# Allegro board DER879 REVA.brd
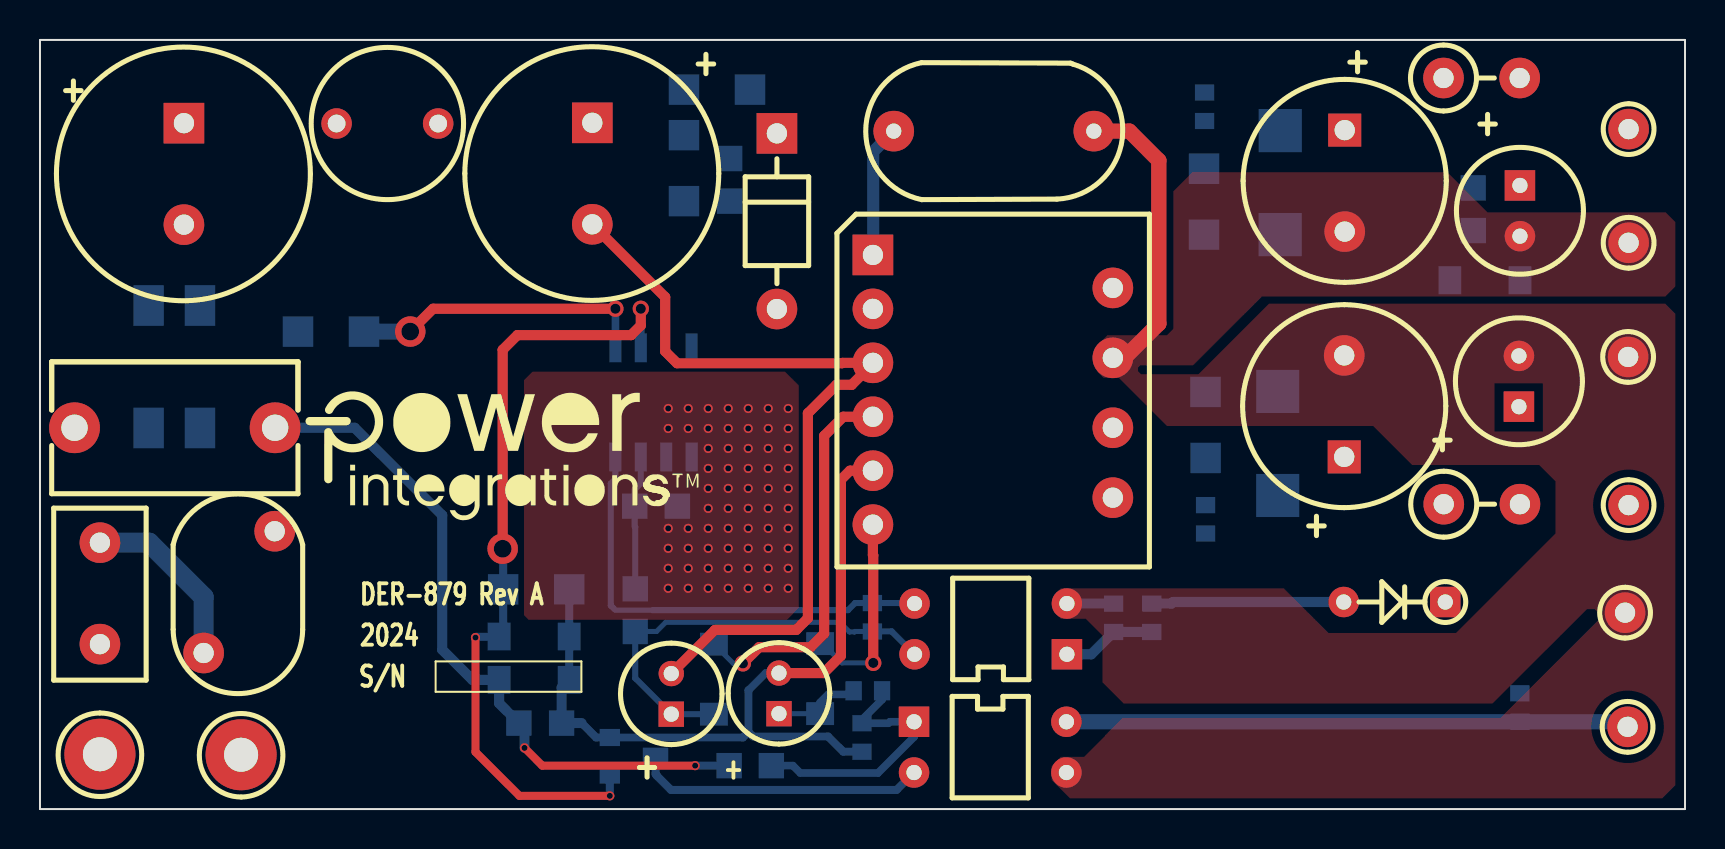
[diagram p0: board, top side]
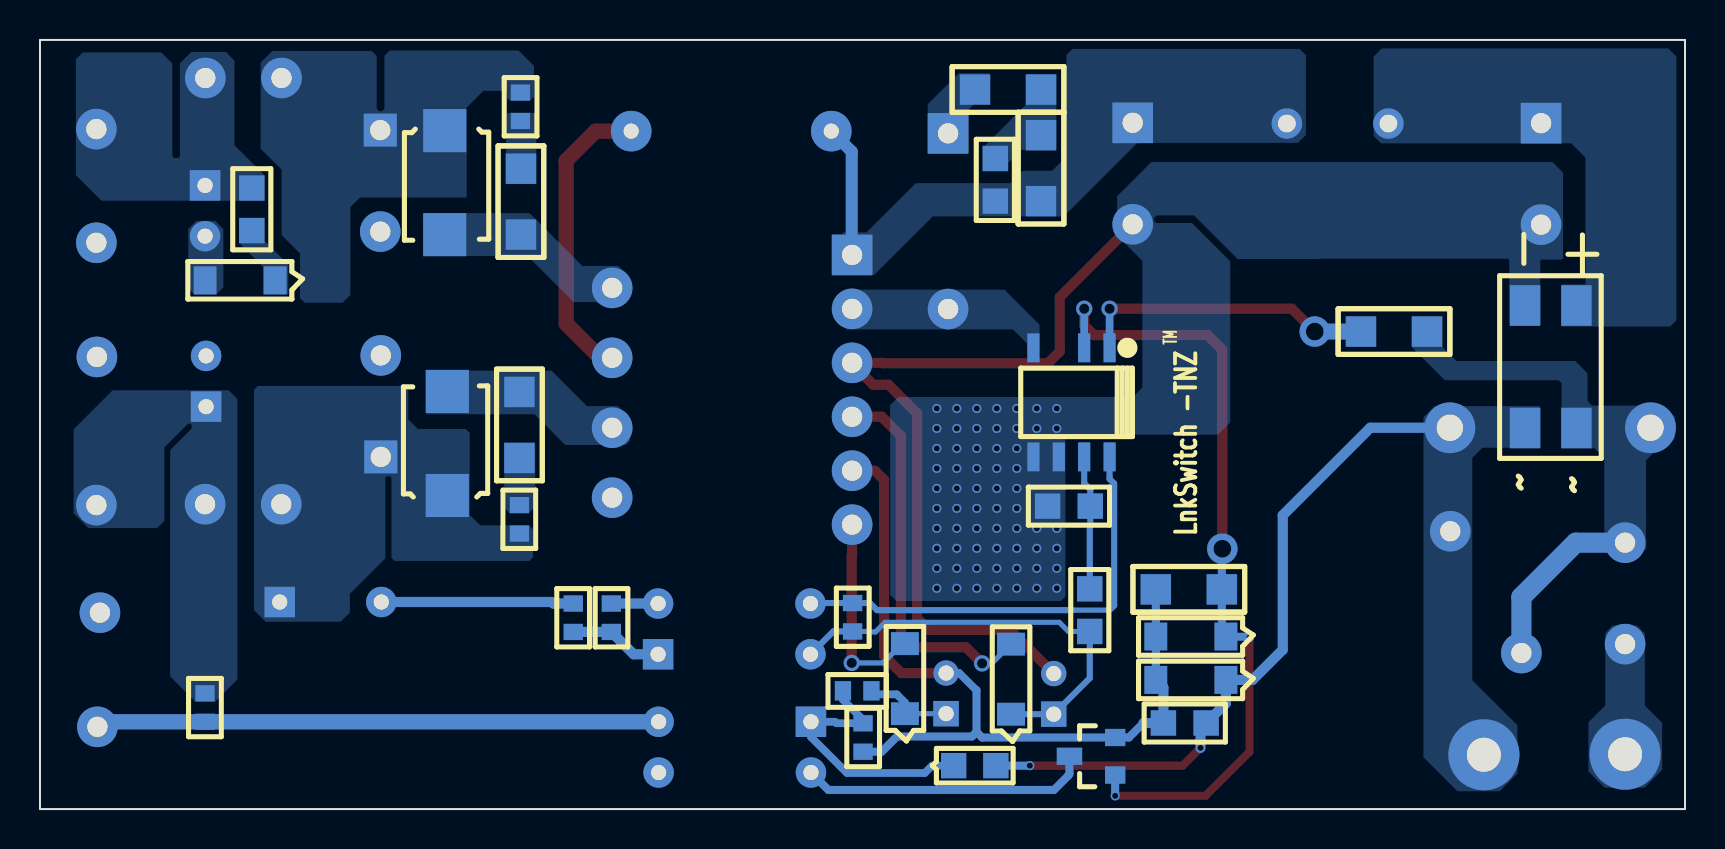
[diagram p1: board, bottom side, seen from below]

Outline 82.27 x 38.5 mm; copper layers: TOP, BOTTOM. Coordinates in mm from the lower left corner of the outline.
Outline path: 0,38.5 0,0 82.27,0 82.27,38.5 0,38.5

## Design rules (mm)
constraint set DEFAULT: min track width 0.508

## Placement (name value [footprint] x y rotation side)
BR1  B10S-G  [PISMSOIC4]  8 19.08 180 bottom
C1  10 uF  [PIPOLCAPCLYD500LS200040]  7.2 34.33 270 top
C2  10 uF  [PIPOLCAPCLYD500LS200040]  27.62 34.35 270 top
C3  2.2 nF  [PISMC0805]  34.49 30.43 90 bottom
C4  1000 pF  [PISMC0603]  58.29 15.21 270 bottom
C5  680 uF  [PIPOLCAPCYLD400LS200040]  65.23 17.63 90 top
C6  120 uF  [PIPOLCAPCYLD250LS100030]  73.96 20.14 90 top
C7  10 uF  [PIPOLCAPCLYD200LS80030]  31.57 4.75 90 top
C8  1 uF  [PISMC0805]  29.74 15.16 0 bottom
C9  1 nF  [PISMC0603]  41.63 8.89 90 bottom
C10  10 uF  [PIPOLCAPCLYD200LS80030]  36.96 4.78 90 top
C11  330 pF  [PINPCAPRAD394X275394030]  42.7 33.93 0 top
C12  680 uF  [PIPOLCAPCYLD400LS200040]  65.25 33.99 270 top
C13  1000 pF  [PISMC0603]  58.24 34.44 90 bottom
C14  120 uF  [PIPOLCAPCYLD250LS100030]  74.02 31.22 270 top
C15  100 nF  [PINPXCAPRAD475X255395040]  1.73 19.09 0 top
C16  100 nF  [PISMC0603]  41.11 2.87 90 bottom
D1  B280-13-F  [PISMSMB]  61.9 15.7 90 bottom
D2  1N4007GP  [PIDV200X110X040DO41]  36.86 34.82 270 top
D3  1N4148W RHG  [PI_SM_SOD-123_12]  33.71 4.75 90 bottom
D4  1N4148W RHG  [PI_SM_SOD-123_12]  39.01 4.78 90 bottom
D5  SS2H10-E3/52T  [PISMSMB]  62.03 33.96 270 bottom
D6  1N4148WS  [PISMDSOD323]  36.58 2.17 180 bottom
F1  1 A  [PI_RST_MICROFUSE]  3 8.26 90 top
L  BLK  [PITPKEYSTONE125X125]  3 2.74 0 top
L1  1 mH  [PICHOKE030DIALS200035]  14.83 34.32 0 top
L2  Ferrite Bead  [PI12WRESD180LS675D040]  70.21 15.26 0 top
L3  Ferrite Bead  [PI12WRESD180LS675D040]  70.19 36.59 0 top
N  WHT  [PITPKEYSTONE125X125]  10.06 2.72 0 top
NOREF  -  []  -228.6 -144.78 0 top
NOREF#2  -  []  -150.78 54.23 0 top
NOREF#3  -  []  82.27 0 90 top
NOREF#4  -  []  13.28 20.88 0 top
NOREF#5  -  []  0 38.5 0 top
Q1  2N7002  [PISMSOT23123_1]  28.5 3.58 90 bottom
R2  51  [PISMR1206]  32.21 36.02 0 bottom
R3  51 k  [PISMR1206]  32.21 30.43 90 bottom
R4  100  [PISMR1206]  58.29 17.58 90 bottom
R5  332  [PISMR0603]  55.6 10.29 270 bottom
R6  1 k  [PISMR0603]  53.7 8.86 90 bottom
R7  51 k  [PISMR0805]  29.77 11.02 270 bottom
R8  510 k  [PISMR1206]  12.9 23.9 0 bottom
R9  240 k  [PISMR1206]  26.47 11 180 bottom
R11  51 k  [PISMR0603]  74.02 5.79 270 bottom
R12  100  [PISMR1206]  58.22 32.05 270 bottom
R13  100  [PISMR0805]  71.68 31.09 270 bottom
R17  510 k  [PISMR0805]  23.95 4.31 0 bottom
R18  1 k  [PISMR0603]  42.11 5.92 180 bottom
RTN_ZCD  BLK  [PITPKEYSTONE100X100]  79.27 9.83 0 top
RV1  300 Vac  [PIDISC350X225LS240X140040]  8.18 7.81 90 top
T1  EE19  [PI_BOBBIN_EE19_10P]  41.66 27.74 0 top
U1  LNK3307  [PISMSO8_NOP3]  28.78 23.09 0 bottom
U2  PS2501-1-H-A  [PI_DIP4]  51.36 7.75 90 top
U3  LTV817D  [PI_DIP4]  43.71 4.37 270 top
UNK5V_RTN  BLK  [PITPKEYSTONE100X100]  79.43 22.63 0 top
UNK12V_RTN  BLK  [PITPKEYSTONE100X100]  79.45 28.35 0 top
UNK+5V  RED  [PITPKEYSTONE100X100]  79.45 15.21 0 top
UNK+12V  RED  [PITPKEYSTONE100X100]  79.45 34.04 0 top
VR2  BZX79-B4V3  [PIDV200X080X030DO35]  70.28 10.36 180 top
VR3  MMSZ4693T1G  [PI_SM_SOD-123_12]  22.96 8.64 0 bottom
VR4  MMSZ5245B-7-F  [PI_SM_SOD-123_12]  70.51 26.47 0 bottom
VR5  MMSZ4693T1G  [PI_SM_SOD-123_12]  22.96 6.46 0 bottom
ZCD  BLUE  [PITPKEYSTONE100X100]  79.4 4.11 0 top

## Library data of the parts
BR1 = DIODE BRIDGE_~~+-: alternate symbols: (pi_sm_soic4_slot)
C1 C2 = CAP POL: alternate symbols: (pipolcapclyd500ls200040800lh)
C3 C4 C8 C9 C11 C13 C16 = CAP NP
C5 C12 = CAP POL: alternate symbols: (pipolcapclyd395x630ls200030h)
C6 C14 = CAP POL: alternate symbols: (pipolcapcyld250ls100030h)
C7 C10 = CAP POL: alternate symbols: (pipolcapclyd200ls80030h)
C15 = CAP NP: alternate symbols: (pinpxcaprad475x255395040_h)
D1 D5 = DIODE SCHOTTKY
D2 = DIODE: alternate symbols: (pidax475x125040do41,pidv200x110x040do41wbead,pidax390x125040do41)
D3 D4 = DIODE: alternate symbols: (pi_sm_sod-123_12_1)
D6 = DIODE
F1 = FUSE: alternate symbols: (pirstmicrofusehoz)
L N RTN_ZCD UNK5V_RTN UNK12V_RTN UNK+5V UNK+12V ZCD = TESTPOINT
L1 = INDUCTOR
L2 L3 = INDUCTOR: alternate symbols: (pi12wvresd180ls150d040,pi12wvresd180ls200d040,pi12wvresd180ls250d040)
Q1 = FET_N_GSD
R2-R9 R11-R13 R17 R18 = R
RV1 = VARISTOR
T1 = BEE19_10P/TF1939
U1 = LNK-TNZ
U2 U3 = OPTO_A_B
VR2 = DIODE_ZENER: alternate symbols: (pidax375x070030do35)
VR3-VR5 = DIODE_ZENER

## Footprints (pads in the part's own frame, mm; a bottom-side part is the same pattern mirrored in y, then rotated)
PI12WRESD180LS675D040
  round 2.032 hole 1.016: 1(0,0) 2(3.81,0)
PI_BOBBIN_EE19_10P
  rect 2.032x2.032 hole 1.016: 1(0,0)
  round 2.032 hole 1.016: 2(0,-2.7) 3(0,-5.4) 4(0,-8.1) 5(0,-10.8) 6(0,-13.5) 7(12,-12.15) 8(12,-8.65) 9(12,-5.15) 10(12,-1.65)
PI_DIP4
  rect 1.524x1.524 hole 0.762: 1(0,0)
  round 1.524 hole 0.762: 2(2.54,0) 3(2.54,7.62) 4(0,7.62)
PI_RST_MICROFUSE
  round 2.032 hole 1.016: 1(0,0) 2(5.08,0)
PI_SM_SOD-123_12
  rect 1.143x1.397 smd: 1(0,0) 2(3.505,0)
PICHOKE030DIALS200035
  round 1.524 hole 0.889: 1(0,0) 2(5.08,0)
PIDISC350X225LS240X140040
  round 2.032 hole 1.016: 1(0,0) 2(6.096,-3.556)
PIDV200X080X030DO35
  rect 1.524x1.524 hole 0.762: 1(0,0)
  round 1.524 hole 0.762: 2(5.08,0)
PIDV200X110X040DO41
  rect 2.032x2.032 hole 1.016: 1(1.001,0)
  round 2.032 hole 1.016: 2(9.794,0)
PINPCAPRAD394X275394030
  round 2.032 hole 0.762: 1(0,0) 2(10.008,0)
PINPXCAPRAD475X255395040
  round 2.54 hole 1.321: 1(0,0) 2(10.033,0)
PIPOLCAPCLYD200LS80030
  rect 1.27x1.27 hole 0.762: 1(0,0)
  round 1.27 hole 0.762: 2(2.032,0)
PIPOLCAPCLYD500LS200040
  rect 2.032x2.032 hole 1.016: 1(0,0)
  round 2.032 hole 1.016: 2(5.08,0)
PIPOLCAPCYLD250LS100030
  rect 1.524x1.524 hole 0.762: 1(0,0)
  round 1.524 hole 0.762: 2(2.54,0)
PIPOLCAPCYLD400LS200040
  rect 1.651x1.651 hole 1.016: 1(0,0)
  round 2.032 hole 1.016: 2(5.08,0)
PISMC0603
  rect 0.813x0.965 smd: 1(0,0) 2(1.422,0)
PISMC0805
  rect 1.27x1.27 smd: 1(0,0) 2(2.134,0)
PISMDSOD323
  rect 1.27x1.27 smd: 1(0,0) 2(2.108,0)
PISMR0603
  rect 0.813x0.965 smd: 1(0,0) 2(1.422,0)
PISMR0805
  rect 1.27x1.27 smd: 1(0,0) 2(2.134,0)
PISMR1206
  rect 1.524x1.524 smd: 1(0,0) 2(3.302,0)
PISMSMB
  rect 2.159x2.159 smd: 1(0,0) 2(5.207,0)
PISMSO8_NOP3
  rect 0.61x1.448 smd: 1(0,0) 2(1.27,0) 4(3.81,0) 5(3.81,5.461) 6(2.54,5.461) 7(1.27,5.461) 8(0,5.461)
PISMSOIC4
  rect 1.524x2.032 smd: 1(0,0) 2(2.571,0) 3(2.571,6.129) 4(0,6.129)
PISMSOT23123_1
  rect 0.864x1.016 smd: 1(-1.88,0) 2(0,0)
  rect 0.864x1.27 smd: 3(-0.94,2.286)
PITPKEYSTONE100X100
  round 2.032 hole 1.016: 1(0,0)
PITPKEYSTONE125X125
  round 3.556 hole 1.702: 1(0,0)

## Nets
ZCD_BIAS: D4.2 T1.6
ZCD_RTN: C10.2 C16.1 Q1.2(S) R9.1 R17.2 T1.5 VR3.2 VR5.2
N4253666: C4.1 R4.1
N4253670: C4.2 C5.1 D1.1 L2.1 VR2.1
N4254079: BR1.4 C1.2 C2.2 C7.2 C8.2 T1.3 U1.5 U1.6
N4254091: C7.1 C9.1 D3.1 R7.2 U2.4
N4254098: C2.1 C3.1 C11.1 L1.2 R3.1 T1.1
N4254129: C3.2 R2.1 R3.2
N4254146: D2.1 R2.2
N4254163: D2.2 T1.2 U1.4
N4254354: C8.1 R7.1 U1.7
N4254668: C9.2 U1.8 U2.3(E)
N4254798: R5.1 VR2.2
N4254829: R5.2 R6.1 U2.1
N4254835: C5.2 C6.2 C11.2 C12.2 C14.2 R6.2 RTN_ZCD.1 T1.9 U2.2 U3.3(E) UNK5V_RTN.1 UNK12V_RTN.1 VR4.2
N4255085: BR1.3 C1.1 L1.1
N4255357: BR1.2 C15.1 F1.2 R8.1 RV1.1
N4255405: BR1.1 C15.2 D6.2 N.1 R17.1 RV1.2 VR5.1
N4255537: R8.2 U1.1
N4259135: Q1.1 R9.2 U1.2 VR3.1
N4259699: R11.2 U3.4 ZCD.1
N4286558: Q1.3 U3.2
N4286955: C10.1 D4.1 R18.2
N4288983: D1.2 R4.2 T1.8
N4289137: C13.1 R12.1
N4289155: D5.2 R12.2 T1.10
N4289170: C12.1 C13.2 D5.1 L3.1
N4289478: C6.1 L2.2 R11.1 UNK+5V.1
N4289689: C14.1 L3.2 R13.1 UNK+12V.1
N4291278: R13.2 VR4.1
N4297184: D3.2 T1.4
N4320314: C16.2 D6.1 R18.1 U3.1
N4330584: F1.1 L.1

Pads without a net: T1 7

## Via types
v1: diameter 0.457, hole 0.305, TOP to BOTTOM, 66 vias
v2: diameter 0.813, hole 0.508, TOP to BOTTOM, 4 vias
v3: diameter 1.524, hole 0.889, TOP to BOTTOM, 2 vias

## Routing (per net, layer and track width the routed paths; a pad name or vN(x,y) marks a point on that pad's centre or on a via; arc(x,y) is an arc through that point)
ZCD_BIAS: length 10
  TOP w0.508: T1.6 41.66,12.71 41.67,12.69 v2(41.67,7.32)
  BOTTOM w0.254: v2(41.67,7.32) 40.11,7.32 39.14,8.28 D4.2
ZCD_RTN: length 40.7
  TOP w0.508: T1.5 40.51,16.94 40.06,16.48 40.06,7.67 39.19,6.81 C10.2
  BOTTOM w0.381: 35.46,5.97 36.3,6.81 C10.2
  BOTTOM w0.399: C16.1 40.17,2.87 39.41,3.63 35.66,3.63 35.43,3.86 ; R9.1 VR3.2 VR5.2 ; 35.43,3.86 35.15,3.58 Q1.2 27.81,3.58 27.09,4.31 ; 35.43,3.86 35.43,5.94 35.46,5.97
  BOTTOM w0.5: 27.09,4.31 R17.2 26.09,6.08 VR5.2
N4254079: length 41.1
  TOP w0.5: 31.86,22.31 40.11,22.31 40.14,22.34 T1.3 ; C7.2 33.76,8.97
  TOP w0.508: C2.2 31.27,25.63 31.27,22.91 31.86,22.31 ; T1.3 41.66,22.3 40.6,21.24 39.83,21.24 38.4,19.81 38.4,9.55 37.82,8.97 33.76,8.97
  BOTTOM w0.399: 27.66,29.23 C2.2
  vias: v1(31.42,20.05) v1(31.42,19.05) v1(31.42,14.05) v1(31.42,13.05) v1(31.42,12.05) v1(31.42,11.05) v1(32.42,20.05) v1(32.42,19.05) v1(32.42,14.05) v1(32.42,13.05) v1(32.42,12.05) v1(32.42,11.05) v1(33.42,20.05) v1(33.42,19.05) v1(33.42,18.05) v1(33.42,17.05) v1(33.42,16.05) v1(33.42,15.05) v1(33.42,14.05) v1(33.42,13.05) v1(33.42,12.05) v1(33.42,11.05) v1(34.42,20.05) v1(34.42,19.05) v1(34.42,18.05) v1(34.42,17.05) v1(34.42,16.05) v1(34.42,15.05) v1(34.42,14.05) v1(34.42,13.05) v1(34.42,12.05) v1(34.42,11.05) v1(35.42,20.05) v1(35.42,19.05) v1(35.42,18.05) v1(35.42,17.05) v1(35.42,16.05) v1(35.42,15.05) v1(35.42,14.05) v1(35.42,13.05) v1(35.42,12.05) v1(35.42,11.05) v1(36.42,20.05) v1(36.42,19.05) v1(36.42,18.05) v1(36.42,17.05) v1(36.42,16.05) v1(36.42,15.05) v1(36.42,14.05) v1(36.42,13.05) v1(36.42,12.05) v1(36.42,11.05) v1(37.42,20.05) v1(37.42,19.05) v1(37.42,18.05) v1(37.42,17.05) v1(37.42,16.05) v1(37.42,15.05) v1(37.42,14.05) v1(37.42,13.05) v1(37.42,12.05) v1(37.42,11.05)
N4254091: length 21.9
  BOTTOM w0.254: R7.2 30.84,8.89 31.29,9.35 40.01,9.35 40.49,8.86 40.74,8.86 40.77,8.89 C9.1
  BOTTOM w0.305: C9.1 42.6,8.89 U2.4 ; R7.2 29.77,6.55 C7.1 D3.1
N4254098: length 6.6
  BOTTOM w0.599: C11.1 41.67,32.91 41.67,27.71
N4254354: length 6.7
  BOTTOM w0.305: R7.1 29.77,14.12 29.74,14.15 C8.1 29.74,16 30.05,16.31 U1.7
N4254668: length 23
  BOTTOM w0.254: 28.7,10.03 28.78,9.96 30.62,9.96
  BOTTOM w0.305: 30.62,9.96 40.41,9.96 40.77,10.31 C9.2 43.71,10.31 43.74,10.29 ; 28.7,10.03 28.55,10.19 28.55,16.29 28.78,16.52 U1.8
N4254798: length 9.6
  BOTTOM w0.508: VR2.2 56.67,10.36 56.59,10.29 R5.1
N4254829: length 4.7
  BOTTOM w0.508: R5.2 R6.1 52.58,7.75 U2.1
N4254835: length 17.3
  TOP w0.762: 53.87,22.21 55.96,24.3 55.96,32.46 54.48,33.93 C11.2
  BOTTOM w0.508: 51.36,10.29 53.7,10.29
N4255357: length 9.3
  BOTTOM w0.399: 1.88,19.24 C15.1
  BOTTOM w1.001: RV1.1 8.18,10.61 5.46,13.34 F1.2
N4255405: length 34.9
  TOP w0.399: v1(32.77,2.17) 25.12,2.17 v1(24.23,3.06)
  BOTTOM w0.399: D6.2 v1(32.77,2.17)
  BOTTOM w0.5: 23.28,4.98 R17.1 24.23,4.03 v1(24.23,3.06)
  BOTTOM w0.508: C15.2 15.74,19.09 20.12,14.71 20.12,7.98 21.63,6.46 VR5.1 22.96,5.3 23.28,4.98
N4255537: length 15
  TOP w0.508: v2(28.78,25.04) 19.66,25.04 v3(18.52,23.9)
  BOTTOM w0.381: v2(28.78,25.04) U1.1
  BOTTOM w0.8: R8.2 v3(18.52,23.9)
N4259135: length 40.3
  TOP w0.399: v1(28.5,0.66) 23.98,0.66 21.78,2.86 v1(21.78,8.59)
  TOP w0.508: v3(23.14,13.03) 23.14,22.99 23.88,23.72 29.57,23.72 30.05,24.21 v2(30.05,25.04)
  BOTTOM w0.381: v2(30.05,25.04) U1.2
  BOTTOM w0.399: v3(23.14,13.03) 23.16,13 R9.2 23.16,8.84 VR3.1 22.95,8.62 21.82,8.62 v1(21.78,8.59) ; v1(28.5,0.66) Q1.1
N4259699: length 28.2
  BOTTOM w0.762: U3.4 R11.2 79.15,4.37 ZCD.1
N4286558: length 14.5
  BOTTOM w0.399: Q1.3 30.78,1.76 30.84,1.71 30.84,1.68 31.56,0.96 42.84,0.96 U3.2
N4286955: length 4.5
  BOTTOM w0.254: C10.1 D4.1
  BOTTOM w0.381: R18.2 40.51,5.74 39.42,5.74 39.01,5.33 D4.1
N4297184: length 19.3
  TOP w0.508: v2(35.15,7.29) 35.97,8.1 38.54,8.1 39.22,8.78 39.22,18.68 40.17,19.64 T1.4
  BOTTOM w0.254: 33.71,8.26 34.67,7.29 v2(35.15,7.29)
N4320314: length 13.5
  BOTTOM w0.381: D6.1 37.66,2.17 38.02,1.8 41.91,1.8 43.71,3.61 U3.1 42.51,4.37 42.43,4.29 C16.2 41.11,4.47 42.11,5.47 R18.1

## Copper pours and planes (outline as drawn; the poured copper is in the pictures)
N4253666 on BOTTOM: 57.5,18.29 57.5,15.11 57.53,15.11 57.84,14.81 58.78,14.81 59.05,15.08 59.05,18.29
N4253670 on BOTTOM: 57.61,12.6 57.78,12.42 64.54,12.42 64.69,12.57 64.69,16.59 64.77,16.66 64.92,16.66 65,16.59 65,12.55 66.78,10.77 66.78,9.83 67.23,9.38 71,9.38 71.57,9.95 71.57,20.99 71.37,21.18 64.08,21.18 63.86,20.95 63.86,19.51 63.37,19.02 60.99,19.02 60.78,18.82 60.78,14.73 60.25,14.2 57.81,14.2 57.61,14
N4254079 on TOP: 37.36,9.47 37.95,10.06 37.95,21.21 37.26,21.89 24.64,21.89 24.21,21.46 24.21,9.7 24.43,9.47
N4254079 on BOTTOM: 6.63,32.38 26.7,32.38 28.4,30.68 28.4,28.7 27.14,27.44 27.14,21.09 27.61,20.62 39.34,20.62 39.75,20.22 39.75,10.72 39.45,10.41 31.22,10.41 30.99,10.64 30.99,18.59 30.84,18.75 23.36,18.75 22.75,19.35 22.75,27.42 24.66,29.34 26.44,29.34 26.57,29.46 26.57,29.57 26.42,29.72 24.56,29.72 22.38,27.53 18.34,27.53 18.33,27.55 8.85,27.55 8.79,27.48 8.79,24.26 7.24,24.26 7.24,27.46 7.19,27.51 6.15,27.51 6.1,27.56 6.1,31.85
N4254098 on BOTTOM: 42.11,26.75 40.54,26.75 37.62,29.67 31.06,29.67 27.38,33.35 19.35,33.35 18.96,33.74 18.96,37.63 18.95,37.64 18.95,37.72 19.28,38.05 30.63,38.05 30.94,37.74 30.94,32.66 31.65,31.95 33.12,31.95 33.74,31.33 38.47,31.33 40.93,28.87 42.08,28.87 42.57,28.37 42.57,27.2
N4254129 on BOTTOM: 31.45,33.07 31.52,32.99 33.2,32.99 33.83,32.36 33.83,31.95 35.13,31.95 35.13,33.2 35.03,33.2 32.97,35.26 32.97,36.75 31.45,36.75
N4254146 on BOTTOM: 37.87,32.84 37.87,35.28 36.32,36.83 34.82,36.83 34.77,36.78 34.77,35.36 34.82,35.31 35.53,35.31 35.84,35 35.84,32.89 35.89,32.84
N4254163 on BOTTOM: 32.89,22.37 32.89,22.36 32.89,22.5 32.89,22.5 32.89,23.29 33.62,24.01 41.93,24.01 42.46,24.55 42.46,25.46 41.92,26 34.04,26 32.28,24.25 32.28,22.37
N4254835 on TOP: 57.63,31.88 70.38,31.88 72.39,29.87 81.31,29.87 81.79,29.39 81.79,26.16 81.28,25.65 61.11,25.65 57.67,22.21 55.03,22.21 54.91,22.1 54.91,21.92 55.07,21.77 57.94,21.77 61.47,25.3 81.28,25.3 81.79,24.79 81.79,1.19 81.13,0.53 51.51,0.53 50.6,1.45 50.6,2.16 51.05,2.62 52.22,2.62 53.26,3.66 53.26,3.68 54.15,4.57 73.05,4.57 77.93,9.45 77.93,9.83 77.75,10.01 77.37,10.01 72.64,5.28 54.2,5.28 53.14,6.35 53.14,8.69 52.3,9.53 51.05,9.53 50.7,9.88 50.7,10.69 51.05,11.05 62.2,11.05 64.44,8.81 70.82,8.81 75.79,13.79 75.79,16.41 74.98,17.22 68.63,17.22 66.67,19.18 56.36,19.18 53.95,21.59 53.19,21.59 52.88,21.89 52.88,23.22 53.39,23.72 56.36,23.72 56.68,24.04 56.68,30.92 ; 3 cut-outs
N4254835 on BOTTOM: 73.1,29.03 73.1,26.11 73.48,25.73 74.52,25.73 74.85,26.06 74.85,29.03 74.45,29.44 73.51,29.44
N4255085 on BOTTOM: 6.17,24.16 0.74,24.16 0.43,24.46 0.43,37.67 0.84,38.07 15.16,38.07 15.57,37.67 15.57,33.68 15.21,33.32 5.69,33.32 4.98,32.61 4.98,26.26 6.15,26.26 6.2,26.21 6.2,24.18
N4255357 on BOTTOM: 6.17,21.31 6.32,21.46 12.01,21.46 13.67,23.11 13.67,24.66 12.14,24.66 12.14,23.14 11.43,22.43 5.49,22.43 4.88,21.82 4.88,20.42 4.65,20.19 1.07,20.19 0.51,19.63 0.51,18.54 1.07,17.98 1.42,17.98 1.96,17.45 1.96,13.54 1.93,13.51 1.93,13.06 2.51,12.47 3.48,12.47 4.04,13.03 4.04,17.58 4.52,18.06 6.15,18.06 6.17,18.08
N4255405 on BOTTOM: 7.24,18.08 10.13,18.08 10.64,17.58 10.64,6.45 8.38,4.19 8.38,1.78 9.27,0.89 11.38,0.89 13.08,2.59 13.08,19.61 12.52,20.17 7.32,20.17 7.24,20.09
N4288983 on BOTTOM: 62.95,21.95 62.95,19.77 62.94,19.76 57.53,19.76 56,18.23 52.97,18.23 52.76,18.44 52.76,19.56 53.37,20.17 54.91,20.17 56.69,21.95
N4289137 on BOTTOM: 57.45,31.29 58.95,31.29 58.96,31.29 58.96,34.8 58.91,34.85 57.53,34.85 57.45,34.77
N4289155 on BOTTOM: 55.58,25.37 57.89,27.69 63.1,27.69 63.1,29.83 63.1,29.83 57.79,29.83 55.14,27.18 53.34,27.18 52.88,26.72 52.88,25.46 53,25.34 53.03,25.37
N4289170 on BOTTOM: 57.57,37.2 57.57,35.65 57.73,35.48 58.8,35.48 58.93,35.61 58.93,35.95 60.09,35.95 60.95,35.1 60.95,32.94 60.93,32.92 60.93,30.64 60.96,30.61 66.27,30.61 66.75,30.12 66.75,25.73 67.13,25.35 69.04,25.35 69.27,25.58 69.27,27.81 70.18,28.73 70.18,32 71.24,33.06 71.24,37.36 70.65,37.95 65.68,37.95 65.43,37.69 65.43,35.05 65.3,34.92 65.18,34.92 65.05,35.05 65.05,37.69 64.77,37.97 58.34,37.97
N4289478 on BOTTOM: 73.51,5.38 74.47,5.38 74.49,5.36 75.76,6.64 75.76,17.97 74.69,19.05 74.69,19.22 74.76,19.29 74.86,19.29 76.05,18.11 76.05,14.43 76.41,14.06 79.84,14.06 80.59,14.81 80.59,19.01 78.64,20.96 72.83,20.96 72.4,20.53 72.4,6.49
N4289689 on BOTTOM: 80.48,31.73 80.48,37.53 80.14,37.87 76.2,37.87 75.66,37.33 75.66,32.69 75.56,32.59 75.36,32.59 75.27,32.67 75.27,37.32 74.7,37.9 72.97,37.9 72.55,37.47 72.55,33.23 71.04,31.72 71.04,30.46 71.04,30.45 79.2,30.45
N4291278 on BOTTOM: 69.85,25.76 71.12,25.76 71.12,27.15 72.31,28.35 72.31,29.59 71.04,29.59 71.04,28.45 69.85,27.25
N4330584 on BOTTOM: 2.03,1.07 4.01,1.07 4.83,1.88 4.83,4.34 3.99,5.18 3.99,8.81 3.62,9.18 2.4,9.18 2.01,8.79 2.01,5.18 1.14,4.32 1.14,1.96

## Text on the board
Ref Des/Silkscreen Bottom: TM | LnkSwitch -TNZ
Ref Des/Silkscreen Top: S/N | DER-879 Rev A | 2024
User.6: 14.  FAB HOUSE LOGO,DATE CODE TO BE IN SILK SCREEN ONLY.DO NOT USE COPPER. | 13.  MATERIAL FR4 COPPER 2oz THICKNESS 0.062"
User.8: FIGURE | FINISHED_SIZE | 12.0 | 20.0 | 30.0 | 35.0 | 40.0 | 52.0 | 67.0 | DRILL CHART: TOP to BOTTOM | ALL UNITS ARE IN MILS | TOLERANCE_DRILL | +3.0/-3.0 | +0.0/-0.0 | PLATED | QTY | 66 | 4 | 20 | 2 | 10 | 24
